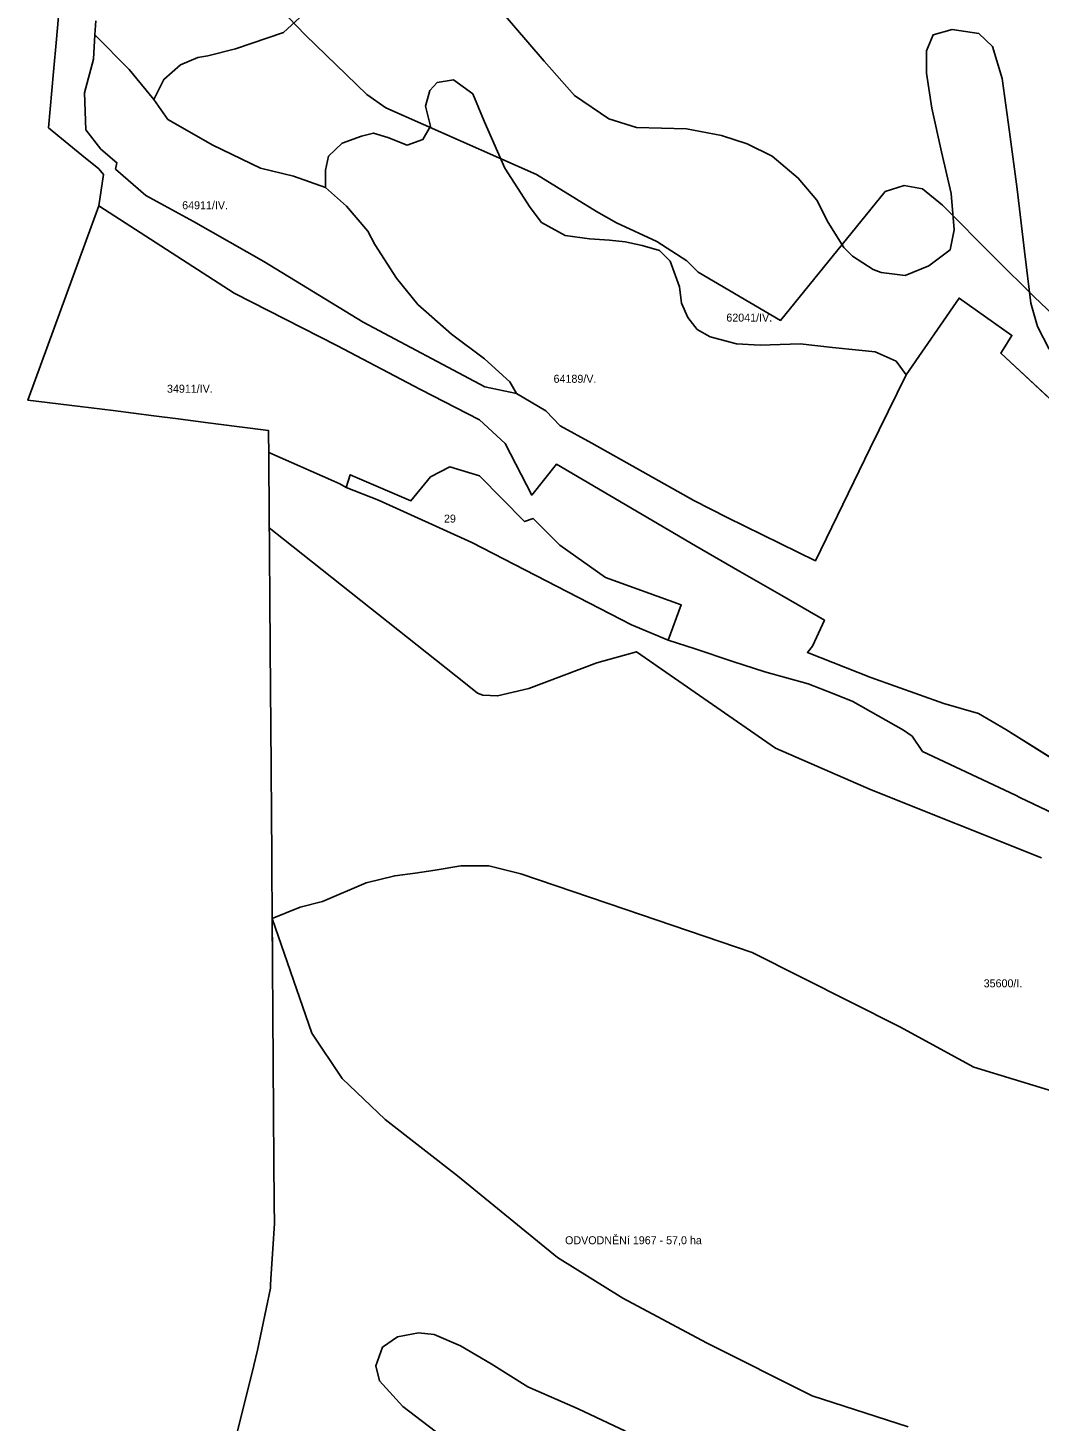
# Model space of a CAD drawing. Extents: x -521621 to -516761, y -1190184 to -1184927.
# Drawn here: x -520810 to -520304, y -1187109 to -1186412 of the extents above; entities that cross this region are included whole.
import ezdxf

# ---------------------------------------------------------------- set-up
doc = ezdxf.new("R2010")
doc.units = 0
doc.layers.add('BPEJ_s', color=7, linetype='Continuous')
doc.layers.add('odvodneni_s', color=7, linetype='Continuous')

msp = doc.modelspace()

# ---------------------------------------------------------------- linework, layer by layer
at = {"layer": 'BPEJ_s'}
for p, q in [((-520795.23, -1186418.02), (-520793.49, -1186398.99)), ((-520775.6, -1186408.89), (-520776.02, -1186415.82)), ((-520796.72, -1186434.3), (-520795.23, -1186418.02)), ((-520776.02, -1186415.82), (-520776.78, -1186428.06)), ((-520776.78, -1186428.06), (-520781.27, -1186444.87)), ((-520799.29, -1186462.32), (-520796.72, -1186434.3)), ((-520781.27, -1186444.87), (-520780.56, -1186463.33)), ((-520782.48, -1186475.98), (-520799.29, -1186462.32)), ((-520780.56, -1186463.33), (-520773, -1186473.04)), ((-520773, -1186473.04), (-520765.02, -1186479.78)), ((-520774.04, -1186482.84), (-520782.48, -1186475.98)), ((-520765.02, -1186479.78), (-520765.77, -1186482.97)), ((-520774.1, -1186501.38), (-520771.73, -1186485.73)), ((-520771.73, -1186485.73), (-520774.04, -1186482.84)), ((-520765.77, -1186482.97), (-520750.6, -1186496.09)), ((-520750.6, -1186496.09), (-520726.8, -1186509.11)), ((-520706.36, -1186544.93), (-520774.1, -1186501.38)), ((-520726.8, -1186509.11), (-520691.56, -1186529.22)), ((-520691.56, -1186529.22), (-520641.95, -1186559.49)), ((-520655.09, -1186571.25), (-520706.36, -1186544.93)), ((-520370.39, -1186585.81), (-520343.94, -1186547.45)), ((-520343.94, -1186547.45), (-520317.49, -1186566.12)), ((-520641.95, -1186559.49), (-520581.07, -1186591.79)), ((-520317.49, -1186566.12), (-520321.8, -1186573.16)), ((-520613.16, -1186593.11), (-520655.09, -1186571.25)), ((-520321.8, -1186573.16), (-520323.03, -1186575)), ((-520323.03, -1186575), (-520279.03, -1186615.98)), ((-520388.36, -1186622.47), (-520370.39, -1186585.81)), ((-520583.63, -1186608.26), (-520613.16, -1186593.11)), ((-520581.07, -1186591.79), (-520565.24, -1186595.23)), ((-520565.24, -1186595.23), (-520550.5, -1186603.82)), ((-520550.5, -1186603.82), (-520543.34, -1186611.4)), ((-520570.89, -1186620.14), (-520583.63, -1186608.26)), ((-520543.34, -1186611.4), (-520527.52, -1186619.99)), ((-520557.58, -1186645.99), (-520570.89, -1186620.14)), ((-520527.52, -1186619.99), (-520476.59, -1186648.62)), ((-520415.75, -1186678.82), (-520388.36, -1186622.47)), ((-520545.23, -1186630.58), (-520557.58, -1186645.99)), ((-520475.65, -1186671.37), (-520545.23, -1186630.58)), ((-520476.59, -1186648.62), (-520459.88, -1186657.23)), ((-520459.88, -1186657.23), (-520415.75, -1186678.82)), ((-520453.54, -1186684.17), (-520475.65, -1186671.37)), ((-520432.52, -1186696.11), (-520453.54, -1186684.17)), ((-520411.28, -1186708.47), (-520432.52, -1186696.11)), ((-520417.13, -1186721.49), (-520411.28, -1186708.47)), ((-520419.71, -1186724.66), (-520417.13, -1186721.49)), ((-520388.1, -1186737.24), (-520419.71, -1186724.66)), ((-520351.47, -1186750.18), (-520388.1, -1186737.24)), ((-520334.23, -1186755.21), (-520351.47, -1186750.18)), ((-520320.58, -1186763.12), (-520334.23, -1186755.21)), ((-520283.95, -1186786.12), (-520320.58, -1186763.12)), ((-520687.22, -1186880.48), (-520687.39, -1186857.68)), ((-520687.39, -1186857.68), (-520687.39, -1186857.68)), ((-520687.39, -1186857.68), (-520667.5, -1186915)), ((-520687.04, -1186905.84), (-520687.22, -1186880.48)), ((-520686.86, -1186929.24), (-520687.04, -1186905.84)), ((-520667.5, -1186915), (-520652.43, -1186937.64)), ((-520686.67, -1186955.53), (-520686.86, -1186929.24)), ((-520652.43, -1186937.64), (-520630.93, -1186958.14)), ((-520686.5, -1186978.43), (-520686.67, -1186955.53)), ((-520630.93, -1186958.14), (-520594.78, -1186986.31)), ((-520686.34, -1187000.29), (-520686.5, -1186978.43)), ((-520594.78, -1186986.31), (-520544.74, -1187027.11)), ((-520686.27, -1187010.16), (-520686.34, -1187000.29)), ((-520687.07, -1187022.85), (-520686.27, -1187010.16)), ((-520688.01, -1187037.85), (-520687.07, -1187022.85)), ((-520544.74, -1187027.11), (-520512, -1187047.51)), ((-520688.21, -1187041.03), (-520688.01, -1187037.85)), ((-520694.7, -1187073.49), (-520688.3, -1187042.53)), ((-520688.3, -1187042.53), (-520688.21, -1187041.03)), ((-520512, -1187047.51), (-520470.27, -1187069.76)), ((-520624.73, -1187066.76), (-520632.23, -1187072.01)), ((-520614.24, -1187064.88), (-520624.73, -1187066.76)), ((-520606.36, -1187065.63), (-520614.24, -1187064.88)), ((-520593.24, -1187071.26), (-520606.36, -1187065.63)), ((-520696.62, -1187081.22), (-520694.7, -1187073.49)), ((-520632.23, -1187072.01), (-520635.61, -1187081.39)), ((-520577.87, -1187080.26), (-520593.24, -1187071.26)), ((-520470.27, -1187069.76), (-520417.41, -1187096.39)), ((-520712.14, -1187143.85), (-520696.62, -1187081.22)), ((-520635.61, -1187081.39), (-520633.73, -1187088.89)), ((-520559.5, -1187091.89), (-520577.87, -1187080.26)), ((-520633.73, -1187088.89), (-520622.11, -1187101.65)), ((-520534.38, -1187102.77), (-520559.5, -1187091.89)), ((-520622.11, -1187101.65), (-520599.61, -1187118.9)), ((-520417.41, -1187096.39), (-520369.42, -1187111.77)), ((-520510.76, -1187114.03), (-520534.38, -1187102.77))]:
    msp.add_line(p, q, dxfattribs=at)
for points in [[(-520665.76, -1186399.98), (-520681.69, -1186414.67), (-520705.74, -1186422.8), (-520719.62, -1186426.36), (-520724.62, -1186427.11), (-520733.24, -1186430.87), (-520741.49, -1186438.12), (-520746.62, -1186448.13), (-520758.87, -1186433.12), (-520776.02, -1186415.82), (-520775.6, -1186408.89)], [(-520279.03, -1186615.98), (-520323.03, -1186575), (-520321.8, -1186573.16), (-520317.49, -1186566.12), (-520343.94, -1186547.45), (-520370.39, -1186585.81), (-520375.37, -1186579.06), (-520385.91, -1186574.37), (-520394.03, -1186573.44), (-520407.15, -1186572.19), (-520423.39, -1186570.31), (-520443.38, -1186570.94), (-520455.25, -1186570.31), (-520468.37, -1186566.87), (-520474.92, -1186563.12), (-520479.61, -1186557.19), (-520482.73, -1186550), (-520483.67, -1186541.87), (-520488.36, -1186529.06), (-520493.66, -1186523.74), (-520502.41, -1186521.24), (-520510.84, -1186519.37), (-520518.65, -1186518.43), (-520528.65, -1186517.81), (-520540.83, -1186516.24), (-520552.7, -1186509.68), (-520558.32, -1186502.18), (-520571.12, -1186482.49), (-520581.43, -1186459.05), (-520587.05, -1186445.3), (-520596.74, -1186438.42), (-520604.86, -1186439.67), (-520608.61, -1186443.74), (-520610.79, -1186451.55), (-520608.29, -1186461.55), (-520612.04, -1186468.11), (-520619.85, -1186470.93), (-520629.53, -1186467.18), (-520636.72, -1186464.99), (-520642.65, -1186466.55), (-520652.33, -1186469.99), (-520659.21, -1186476.55), (-520660.77, -1186483.43), (-520660.77, -1186492.18), (-520676.7, -1186486.55), (-520693.25, -1186482.49), (-520716.99, -1186470.93), (-520739.48, -1186458.11), (-520746.62, -1186448.13), (-520741.49, -1186438.12), (-520733.24, -1186430.87), (-520724.62, -1186427.11), (-520719.62, -1186426.36), (-520705.74, -1186422.8), (-520681.69, -1186414.67), (-520665.76, -1186399.98)], [(-520573.94, -1186402.79), (-520551.45, -1186429.05), (-520536.14, -1186446.24), (-520518.96, -1186457.8), (-520505.22, -1186462.18), (-520480.23, -1186462.8), (-520462.74, -1186466.24), (-520449.94, -1186470.3), (-520437.44, -1186476.55), (-520424.33, -1186487.49), (-520414.96, -1186498.43), (-520409.33, -1186509.68), (-520401.52, -1186522.18), (-520397.15, -1186526.56), (-520386.84, -1186533.12), (-520382.78, -1186534.68), (-520370.79, -1186536.18), (-520359.07, -1186531.39), (-520348.43, -1186523.4), (-520346.3, -1186513.27), (-520347.89, -1186495.16), (-520352.68, -1186474.38), (-520357.48, -1186452.54), (-520360.14, -1186434.96), (-520360.14, -1186423.77), (-520356.94, -1186415.78), (-520347.36, -1186413.11), (-520334.05, -1186415.24), (-520327.13, -1186421.64), (-520322.34, -1186437.62), (-520318.61, -1186464.26), (-520314.88, -1186493.03), (-520311.15, -1186523.93), (-520307.96, -1186550.03), (-520304.77, -1186561.75), (-520298.91, -1186572.94)], [(-520298.91, -1186572.94), (-520304.77, -1186561.75), (-520307.96, -1186550.03), (-520311.15, -1186523.93), (-520314.88, -1186493.03), (-520318.61, -1186464.26), (-520322.34, -1186437.62), (-520327.13, -1186421.64), (-520334.05, -1186415.24), (-520347.36, -1186413.11), (-520356.94, -1186415.78), (-520360.14, -1186423.77), (-520360.14, -1186434.96), (-520357.48, -1186452.54), (-520352.68, -1186474.38), (-520347.89, -1186495.16), (-520346.3, -1186513.27), (-520348.43, -1186523.4), (-520359.07, -1186531.39), (-520370.79, -1186536.18), (-520382.78, -1186534.68), (-520386.84, -1186533.12), (-520397.15, -1186526.56), (-520401.52, -1186522.18), (-520409.33, -1186509.68), (-520414.96, -1186498.43), (-520424.33, -1186487.49), (-520437.44, -1186476.55), (-520449.94, -1186470.3), (-520462.74, -1186466.24), (-520480.23, -1186462.8), (-520505.22, -1186462.18), (-520518.96, -1186457.8), (-520536.14, -1186446.24), (-520551.45, -1186429.05), (-520573.94, -1186402.79)], [(-520280.59, -1186812.77), (-520313.26, -1186797.34), (-520315.69, -1186795.92), (-520362.15, -1186774.19), (-520367.43, -1186766.47), (-520371.69, -1186763.43), (-520397.08, -1186749.1), (-520406.45, -1186745.33), (-520419.37, -1186740.25), (-520440.98, -1186734.31), (-520457.08, -1186729.23), (-520475.93, -1186722.87), (-520489.38, -1186718.55), (-520482.81, -1186700.88), (-520520.74, -1186687.21), (-520543.5, -1186670.94), (-520556.91, -1186657.62), (-520561.17, -1186659.22), (-520583.75, -1186636.35), (-520598.62, -1186631.82), (-520608.19, -1186636.88), (-520618.02, -1186648.85), (-520648.31, -1186635.81), (-520650.43, -1186642.2), (-520653.62, -1186640.34), (-520656.54, -1186639.01), (-520689.1, -1186624.61), (-520689.11, -1186623.84), (-520689.11, -1186623.07), (-520689.12, -1186622.14), (-520689.13, -1186621.21), (-520689.14, -1186619.31), (-520689.15, -1186617.42), (-520689.17, -1186615.55), (-520689.18, -1186613.67), (-520703.76, -1186611.79), (-520720.68, -1186609.6), (-520734.44, -1186607.83), (-520746.56, -1186606.26), (-520766.82, -1186603.65), (-520783.43, -1186601.67), (-520809.55, -1186598.56), (-520774.1, -1186501.38), (-520706.36, -1186544.93), (-520655.09, -1186571.25), (-520613.16, -1186593.11), (-520583.63, -1186608.26), (-520570.89, -1186620.14), (-520557.58, -1186645.99), (-520545.23, -1186630.58), (-520475.65, -1186671.37), (-520453.54, -1186684.17), (-520432.52, -1186696.11), (-520411.28, -1186708.47), (-520417.13, -1186721.49), (-520419.71, -1186724.66), (-520388.1, -1186737.24), (-520351.47, -1186750.18), (-520334.23, -1186755.21), (-520320.58, -1186763.12), (-520283.95, -1186786.12)], [(-520689.1, -1186624.61), (-520656.54, -1186639.01), (-520653.62, -1186640.34), (-520650.43, -1186642.2), (-520634.23, -1186648.58), (-520587.47, -1186669.59), (-520507.76, -1186710.81), (-520489.38, -1186718.55), (-520475.93, -1186722.87), (-520457.08, -1186729.23), (-520440.98, -1186734.31), (-520419.37, -1186740.25), (-520406.45, -1186745.33), (-520397.08, -1186749.1), (-520371.69, -1186763.43), (-520367.43, -1186766.47), (-520362.15, -1186774.19), (-520315.69, -1186795.92), (-520313.26, -1186797.34), (-520280.59, -1186812.77)], [(-520687.39, -1186857.68), (-520687.39, -1186857.68), (-520687.42, -1186853.11), (-520687.55, -1186835.51), (-520687.59, -1186830.55), (-520687.63, -1186824.51), (-520687.76, -1186806.97), (-520687.95, -1186781.61), (-520688.38, -1186722.47), (-520688.41, -1186719.18), (-520688.45, -1186713.07), (-520688.49, -1186707.23), (-520688.53, -1186701.65), (-520688.57, -1186697.28), (-520688.6, -1186692.91), (-520688.63, -1186688.29), (-520688.66, -1186684.66), (-520688.69, -1186680.16), (-520688.72, -1186675.77), (-520688.74, -1186673.62), (-520688.76, -1186671.1), (-520688.79, -1186666.09), (-520688.82, -1186662.26), (-520688.85, -1186657.85), (-520688.88, -1186654.64), (-520688.91, -1186650.76), (-520688.94, -1186646.62), (-520688.97, -1186642.4), (-520688.98, -1186640.76), (-520688.99, -1186638.57), (-520689.04, -1186631.79), (-520689.1, -1186624.61)], [(-520369.42, -1187111.77), (-520417.41, -1187096.39), (-520470.27, -1187069.76), (-520512, -1187047.51), (-520544.74, -1187027.11), (-520594.78, -1186986.31), (-520630.93, -1186958.14), (-520652.43, -1186937.64), (-520667.5, -1186915), (-520687.39, -1186857.68), (-520673.4, -1186852.01), (-520662.28, -1186849.23), (-520640.34, -1186839.8), (-520626.13, -1186836.25), (-520615.94, -1186835.01), (-520605.89, -1186833.49), (-520592.97, -1186831.26), (-520579.11, -1186831.26), (-520563.01, -1186835.38), (-520510.96, -1186852.99), (-520447.31, -1186874.72), (-520373.55, -1186911.81), (-520336.48, -1186932.05), (-520293.42, -1186945.16)], [(-520293.42, -1186945.16), (-520336.48, -1186932.05), (-520373.55, -1186911.81), (-520447.31, -1186874.72), (-520510.96, -1186852.99), (-520563.01, -1186835.38), (-520579.11, -1186831.26), (-520592.97, -1186831.26), (-520605.89, -1186833.49), (-520615.94, -1186835.01), (-520626.13, -1186836.25), (-520640.34, -1186839.8), (-520662.28, -1186849.23), (-520673.4, -1186852.01), (-520687.39, -1186857.68)], [(-520599.61, -1187118.9), (-520622.11, -1187101.65), (-520633.73, -1187088.89), (-520635.61, -1187081.39), (-520632.23, -1187072.01), (-520624.73, -1187066.76), (-520614.24, -1187064.88), (-520606.36, -1187065.63), (-520593.24, -1187071.26), (-520577.87, -1187080.26), (-520559.5, -1187091.89), (-520534.38, -1187102.77), (-520510.76, -1187114.03)]]:
    msp.add_lwpolyline(points, dxfattribs=at)
for points in [[(-520776.02, -1186415.82), (-520758.87, -1186433.12), (-520746.62, -1186448.13), (-520739.48, -1186458.11), (-520716.99, -1186470.93), (-520693.25, -1186482.49), (-520676.7, -1186486.55), (-520660.77, -1186492.18), (-520650.15, -1186501.55), (-520639.53, -1186514.06), (-520636.09, -1186520.62), (-520625.19, -1186537.5), (-520614.5, -1186550.66), (-520597.66, -1186565.45), (-520581.23, -1186577.79), (-520568.49, -1186589.3), (-520565.24, -1186595.23), (-520581.07, -1186591.79), (-520641.95, -1186559.49), (-520691.56, -1186529.22), (-520726.8, -1186509.11), (-520750.6, -1186496.09), (-520765.77, -1186482.97), (-520765.02, -1186479.78), (-520773, -1186473.04), (-520780.56, -1186463.33), (-520781.27, -1186444.87), (-520776.78, -1186428.06)], [(-520660.77, -1186492.18), (-520660.77, -1186483.43), (-520659.21, -1186476.55), (-520652.33, -1186469.99), (-520642.65, -1186466.55), (-520636.72, -1186464.99), (-520629.53, -1186467.18), (-520619.85, -1186470.93), (-520612.04, -1186468.11), (-520608.29, -1186461.55), (-520610.79, -1186451.55), (-520608.61, -1186443.74), (-520604.86, -1186439.67), (-520596.74, -1186438.42), (-520587.05, -1186445.3), (-520581.43, -1186459.05), (-520571.12, -1186482.49), (-520558.32, -1186502.18), (-520552.7, -1186509.68), (-520540.83, -1186516.24), (-520528.65, -1186517.81), (-520518.65, -1186518.43), (-520510.84, -1186519.37), (-520502.41, -1186521.24), (-520493.66, -1186523.74), (-520488.36, -1186529.06), (-520483.67, -1186541.87), (-520482.73, -1186550), (-520479.61, -1186557.19), (-520474.92, -1186563.12), (-520468.37, -1186566.87), (-520455.25, -1186570.31), (-520443.38, -1186570.94), (-520423.39, -1186570.31), (-520407.15, -1186572.19), (-520394.03, -1186573.44), (-520385.91, -1186574.37), (-520375.37, -1186579.06), (-520370.39, -1186585.81), (-520388.36, -1186622.47), (-520415.75, -1186678.82), (-520459.88, -1186657.23), (-520476.59, -1186648.62), (-520527.52, -1186619.99), (-520543.34, -1186611.4), (-520550.5, -1186603.82), (-520565.24, -1186595.23), (-520568.49, -1186589.3), (-520581.23, -1186577.79), (-520597.66, -1186565.45), (-520614.5, -1186550.66), (-520625.19, -1186537.5), (-520636.09, -1186520.62), (-520639.53, -1186514.06), (-520650.15, -1186501.55)], [(-520650.43, -1186642.2), (-520648.31, -1186635.81), (-520618.02, -1186648.85), (-520608.19, -1186636.88), (-520598.62, -1186631.82), (-520583.75, -1186636.35), (-520561.17, -1186659.22), (-520556.91, -1186657.62), (-520543.5, -1186670.94), (-520520.74, -1186687.21), (-520482.81, -1186700.88), (-520489.38, -1186718.55), (-520507.76, -1186710.81), (-520587.47, -1186669.59), (-520634.23, -1186648.58)]]:
    msp.add_lwpolyline(points, close=True, dxfattribs=at)
at = {"layer": 'odvodneni_s'}
for points in [[(-520259.28, -1186591.36), (-520306.17, -1186546.93), (-520325.99, -1186527.4), (-520352.24, -1186500.97), (-520362.26, -1186492.86), (-520371.32, -1186491.19), (-520380.8, -1186494.24), (-520433.27, -1186558.6), (-520474.32, -1186534.58), (-520480.05, -1186528.86), (-520495.12, -1186519.09), (-520515.23, -1186509.87), (-520525.28, -1186504.15), (-520555.21, -1186485.71), (-520630.57, -1186452.32), (-520640.11, -1186445.64), (-520670.64, -1186416.07), (-520679.29, -1186407.25)], [(-520302.62, -1186827.36), (-520387.86, -1186793.32), (-520435.64, -1186772.42), (-520505.25, -1186724.26), (-520525.02, -1186729.9), (-520559.07, -1186742.62), (-520574.71, -1186746.39), (-520581.97, -1186745.97), (-520584.76, -1186745), (-520590.63, -1186740.11), (-520681.8, -1186667.92), (-520688.82, -1186662.26), (-520688.79, -1186666.09), (-520688.76, -1186671.1), (-520688.74, -1186673.62), (-520688.72, -1186675.77), (-520688.69, -1186680.16), (-520688.66, -1186684.66), (-520688.63, -1186688.29), (-520688.6, -1186692.91), (-520688.58, -1186695.6), (-520688.57, -1186697.28), (-520688.53, -1186701.65), (-520688.49, -1186707.23), (-520688.45, -1186713.07), (-520688.41, -1186719.18), (-520688.38, -1186722.47), (-520687.95, -1186781.61), (-520687.76, -1186806.97), (-520687.63, -1186824.51), (-520687.59, -1186830.55), (-520687.55, -1186835.51), (-520687.42, -1186853.11), (-520687.22, -1186880.48), (-520687.04, -1186905.84), (-520686.86, -1186929.24), (-520686.67, -1186955.53), (-520686.5, -1186978.43), (-520686.34, -1187000.29), (-520686.27, -1187010.16), (-520687.07, -1187022.85), (-520688.01, -1187037.85), (-520688.21, -1187041.03), (-520688.3, -1187042.53), (-520694.7, -1187073.49), (-520696.62, -1187081.22), (-520712.14, -1187143.85)]]:
    msp.add_lwpolyline(points, dxfattribs=at)

# ---------------------------------------------------------------- texts
at = {"layer": 'BPEJ_s'}
for s, p in [('64911/IV.', (-520732.38, -1186503.05)), ('62041/IV.', (-520460.27, -1186559.22)), ('64189/V.', (-520546.67, -1186589.81)), ('34911/IV.', (-520739.98, -1186594.78)), ('29', (-520601.47, -1186659.72)), ('35600/I.', (-520331.6, -1186892.06))]:
    msp.add_text(s, height=4, dxfattribs=at).set_placement(p)
at = {"layer": 'odvodneni_s'}
msp.add_text('ODVODNĚNí 1967 - 57,0 ha', height=4, dxfattribs=at).set_placement((-520540.92, -1187020.53))

doc.saveas('drawing.dxf')
